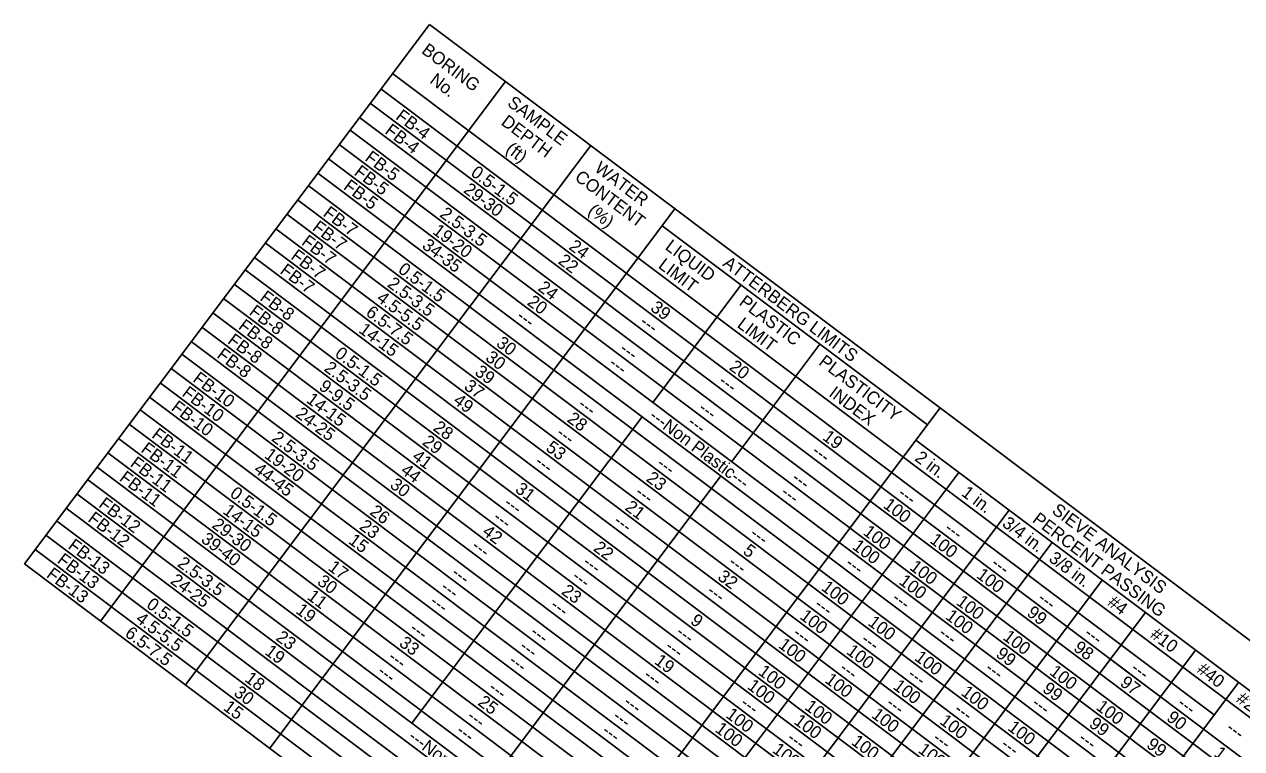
# Model space of a CAD drawing. Extents: x 627484.2 to 627517.5, y 367968.7 to 367996.9.
# Drawn here: x 627505.88 to 627511.18, y 367978.6 to 367981.76 of the extents above; entities that cross this region are included whole.
import ezdxf

# ---------------------------------------------------------------- set-up
doc = ezdxf.new("R2010")
doc.units = 0
doc.layers.add('Default', color=7, linetype='Continuous')
doc.layers.add('R_Survey Control', color=7, linetype='Continuous')

msp = doc.modelspace()

# ---------------------------------------------------------------- linework, layer by layer
at = {"layer": 'Default'}
for p, q in [((627505.8846, 367979.4086), (627507.6468, 367981.7554)), ((627507.6468, 367981.7554), (627512.1221, 367978.3948)), ((627507.4858, 367981.5409), (627511.9611, 367978.1804)), ((627506.216, 367979.1598), (627507.9782, 367981.5065)), ((627507.4361, 367981.4747), (627511.0615, 367978.7523)), ((627507.3892, 367981.4123), (627510.8275, 367978.8305)), ((627507.3424, 367981.3499), (627511.8177, 367977.9894)), ((627507.3014, 367981.2954), (627511.7767, 367977.9348)), ((627506.5863, 367978.8817), (627508.3485, 367981.2284)), ((627507.2546, 367981.233), (627511.7298, 367977.8725)), ((627507.2078, 367981.1706), (627511.683, 367977.8101)), ((627507.1609, 367981.1082), (627511.6362, 367977.7477)), ((627507.1199, 367981.0537), (627511.5952, 367977.6932)), ((627507.0731, 367980.9913), (627511.5483, 367977.6308)), ((627506.9528, 367978.6065), (627508.715, 367980.9533)), ((627507.0263, 367980.9289), (627511.5015, 367977.5684)), ((627508.6594, 367980.8792), (627509.8133, 367980.0127)), ((627506.9794, 367980.8665), (627511.4547, 367977.506)), ((627506.9326, 367980.8042), (627511.4078, 367977.4437)), ((627506.8858, 367980.7418), (627511.361, 367977.3813)), ((627506.8448, 367980.6872), (627511.32, 367977.3267)), ((627506.7979, 367980.6248), (627511.2732, 367977.2643)), ((627508.6189, 367980.1109), (627509.0024, 367980.6216)), ((627506.7511, 367980.5625), (627511.2264, 367977.202)), ((627506.7043, 367980.5001), (627511.1795, 367977.1396)), ((627506.6574, 367980.4377), (627511.1327, 367977.0772)), ((627506.6106, 367980.3754), (627511.0858, 367977.0149)), ((627508.962, 367979.8533), (627509.3455, 367980.364)), ((627506.5696, 367980.3208), (627511.0449, 367976.9603)), ((627506.5228, 367980.2584), (627510.998, 367976.8979)), ((627506.4759, 367980.196), (627510.9512, 367976.8355)), ((627506.4291, 367980.1337), (627510.9044, 367976.7732)), ((627508.1067, 367977.74), (627509.8689, 367980.0868)), ((627506.3881, 367980.0791), (627510.8634, 367976.7186)), ((627507.571, 367978.7153), (627508.5721, 367980.0486)), ((627506.3413, 367980.0167), (627510.8165, 367976.6562)), ((627506.2944, 367979.9543), (627510.7697, 367976.5938)), ((627509.7635, 367979.9465), (627511.354, 367978.7521)), ((627506.2476, 367979.892), (627510.7229, 367976.5315)), ((627506.2008, 367979.8296), (627510.676, 367976.4691)), ((627506.1598, 367979.775), (627510.635, 367976.4145)), ((627507.914, 367978.4577), (627508.9152, 367979.791)), ((627508.2938, 367977.5995), (627509.9506, 367979.806)), ((627506.113, 367979.7126), (627510.5882, 367976.3521)), ((627506.0661, 367979.6503), (627510.5414, 367976.2898)), ((627508.5121, 367977.4356), (627510.1689, 367979.642)), ((627506.0251, 367979.5957), (627510.5004, 367976.2352)), ((627505.9783, 367979.5333), (627510.4536, 367976.1728)), ((627508.6992, 367977.2951), (627510.356, 367979.5015)), ((627505.9315, 367979.4709), (627510.4067, 367976.1104)), ((627505.8846, 367979.4086), (627510.3599, 367976.0481)), ((627508.9175, 367977.1312), (627510.5743, 367979.3376)), ((627509.1046, 367976.9907), (627510.7615, 367979.1971)), ((627509.3229, 367976.8267), (627510.9798, 367979.0332)), ((627510.6092, 367978.9944), (627511.8645, 367978.0518)), ((627509.51, 367976.6862), (627511.1669, 367978.8927))]:
    msp.add_line(p, q, dxfattribs=at)
at = {"layer": 'R_Survey Control'}
msp.add_line((627507.6468, 367981.7554), (627507.6468, 367981.7554), dxfattribs=at)

# ---------------------------------------------------------------- texts
at = {"layer": 'Default'}
for s, p in [('BORING', (627507.6087, 367981.6335)), ('No.', (627507.6443, 367981.5037)), ('SAMPLE', (627507.9818, 367981.4049)), ('FB-4', (627507.4962, 367981.3464)), ('DEPTH', (627507.9549, 367981.322)), ('FB-4', (627507.4493, 367981.284)), ('FB-5', (627507.3625, 367981.1663)), ('(ft)', (627507.9748, 367981.2039)), ('FB-5', (627507.3157, 367981.1039)), ('0.5-1.5', (627507.8228, 367981.1011)), ('WATER', (627508.3611, 367981.1201)), ('CONTENT', (627508.2751, 367981.0816)), ('FB-5', (627507.2689, 367981.0416)), ('29-30', (627507.7912, 367981.0273)), ('FB-7', (627507.1804, 367980.9251)), ('2.5-3.5', (627507.6881, 367980.9218)), ('(%)', (627508.3323, 367980.9354)), ('FB-7', (627507.1335, 367980.8628)), ('19-20', (627507.6565, 367980.848)), ('FB-7', (627507.0867, 367980.8004)), ('34-35', (627507.6107, 367980.7849)), ('FB-7', (627507.0399, 367980.738)), ('24', (627508.2497, 367980.7806)), ('LIQUID', (627508.6685, 367980.7798)), ('FB-7', (627506.993, 367980.6756)), ('0.5-1.5', (627507.5066, 367980.6801)), ('22', (627508.2031, 367980.718)), ('LIMIT', (627508.6387, 367980.699)), ('ATTERBERG LIMITS', (627508.9191, 367980.7077)), ('2.5-3.5', (627507.4598, 367980.6177)), ('24', (627508.115, 367980.6012)), ('FB-8', (627506.9056, 367980.5584)), ('4.5-5.5', (627507.413, 367980.5554)), ('20', (627508.0682, 367980.5388)), ('PLASTIC', (627508.9903, 367980.5382)), ('FB-8', (627506.8588, 367980.496)), ('6.5-7.5', (627507.3661, 367980.493)), ('39', (627508.6047, 367980.514)), ('FB-8', (627506.8119, 367980.4336)), ('14-15', (627507.3355, 367980.4184)), ('---', (627508.0216, 367980.4764)), ('---', (627508.5578, 367980.4517)), ('LIMIT', (627508.9817, 367980.4414)), ('FB-8', (627506.7651, 367980.3713)), ('FB-8', (627506.7183, 367980.3089)), ('0.5-1.5', (627507.2315, 367980.3137)), ('30', (627507.9336, 367980.3595)), ('---', (627508.47, 367980.3347)), ('30', (627507.8868, 367980.2971)), ('20', (627508.9475, 367980.2566)), ('PLASTICITY', (627509.3365, 367980.2782)), ('FB-10', (627506.6135, 367980.2047)), ('2.5-3.5', (627507.1846, 367980.2513)), ('39', (627507.8401, 367980.2346)), ('---', (627508.4231, 367980.2723)), ('9-9.5', (627507.1622, 367980.1706)), ('37', (627507.7934, 367980.1722)), ('---', (627508.9008, 367980.1941)), ('FB-10', (627506.5667, 367980.1423)), ('14-15', (627507.1072, 367980.1144)), ('49', (627507.7465, 367980.1099)), ('INDEX', (627509.3808, 367980.1418)), ('FB-10', (627506.5198, 367980.0799)), ('24-25', (627507.0604, 367980.052)), ('---', (627508.2885, 367980.093)), ('---', (627508.813, 367980.0771)), ('28', (627507.6591, 367979.9926)), ('28', (627508.2422, 367980.0302)), ('---Non Plastic---', (627508.5986, 367980.0431)), ('---', (627508.7662, 367980.0147)), ('FB-11', (627506.4348, 367979.9608)), ('2.5-3.5', (627506.9563, 367979.9472)), ('---', (627508.1948, 367979.9683)), ('19', (627509.3532, 367979.9519)), ('FB-11', (627506.388, 367979.8985)), ('29', (627507.6118, 367979.9305)), ('53', (627508.1494, 367979.9049)), ('FB-11', (627506.3412, 367979.8361)), ('19-20', (627506.9247, 367979.8734)), ('41', (627507.5676, 367979.8662)), ('---', (627509.3063, 367979.8896)), ('2 in.', (627509.7545, 367979.8609)), ('44-45', (627506.8789, 367979.8103)), ('44', (627507.5179, 367979.806)), ('---', (627508.1011, 367979.8435)), ('---', (627508.6315, 367979.8354)), ('FB-11', (627506.2943, 367979.7737)), ('30', (627507.4711, 367979.7436)), ('23', (627508.5861, 367979.772)), ('---', (627509.2185, 367979.7727)), ('0.5-1.5', (627506.7748, 367979.7055)), ('31', (627508.016, 367979.7246)), ('---', (627508.5379, 367979.7107)), ('---', (627509.1716, 367979.7103)), ('---', (627509.6806, 367979.7061)), ('1 in.', (627509.9572, 367979.7087)), ('FB-12', (627506.2039, 367979.6588)), ('14-15', (627506.7442, 367979.631)), ('26', (627507.3833, 367979.6266)), ('---', (627507.9665, 367979.6642)), ('21', (627508.4937, 367979.6463)), ('100', (627509.6173, 367979.6561)), ('SIEVE ANALYSIS', (627510.3508, 367979.6324)), ('FB-12', (627506.157, 367979.5964)), ('29-30', (627506.6964, 367979.5694)), ('---', (627507.9197, 367979.6018)), ('---', (627508.4442, 367979.5859)), ('3/4 in.', (627510.1346, 367979.5755)), ('PERCENT PASSING', (627510.266, 367979.5929)), ('23', (627507.338, 367979.5631)), ('42', (627507.8729, 367979.5394)), ('100', (627509.5295, 367979.5391)), ('---', (627509.8833, 367979.5539)), ('FB-13', (627506.0706, 367979.4784)), ('39-40', (627506.6496, 367979.507)), ('15', (627507.2906, 367979.5012)), ('22', (627508.3564, 367979.469)), ('---', (627509.037, 367979.531)), ('100', (627509.4827, 367979.4767)), ('100', (627509.82, 367979.5038)), ('FB-13', (627506.0237, 367979.4161)), ('---', (627507.826, 367979.4771)), ('5', (627509.0072, 367979.4558)), ('3/8 in.', (627510.3373, 367979.4233)), ('FB-13', (627505.9769, 367979.3537)), ('2.5-3.5', (627506.5465, 367979.4015)), ('17', (627507.2021, 367979.3847)), ('---', (627508.3095, 367979.4066)), ('---', (627508.9433, 367979.4062)), ('---', (627509.4522, 367979.402)), ('100', (627509.7322, 367979.3869)), ('---', (627510.086, 367979.4017)), ('24-25', (627506.5159, 367979.3269)), ('30', (627507.1549, 367979.3226)), ('---', (627507.7382, 367979.3601)), ('---', (627508.2627, 367979.3442)), ('32', (627508.8965, 367979.3438)), ('100', (627509.6854, 367979.3245)), ('100', (627510.0227, 367979.3516)), ('11', (627507.1109, 367979.2581)), ('---', (627507.6913, 367979.2978)), ('23', (627508.2173, 367979.2808)), ('---', (627508.8496, 367979.2815)), ('100', (627509.348, 367979.2974)), ('0.5-1.5', (627506.4118, 367979.2222)), ('---', (627507.6445, 367979.2354)), ('---', (627508.169, 367979.2195)), ('---', (627509.3176, 367979.2227)), ('---', (627509.655, 367979.2498)), ('100', (627509.9349, 367979.2347)), ('---', (627510.2887, 367979.2495)), ('#4', (627510.5924, 367979.2318)), ('4.5-5.5', (627506.365, 367979.1598)), ('19', (627507.0615, 367979.1977)), ('9', (627508.7781, 367979.1523)), ('100', (627509.2543, 367979.1727)), ('100', (627509.8881, 367979.1723)), ('99', (627510.2419, 367979.187)), ('6.5-7.5', (627506.3182, 367979.0974)), ('---', (627507.5567, 367979.1184)), ('100', (627509.5507, 367979.1452)), ('#10', (627510.7787, 367979.0919)), ('23', (627506.975, 367979.0797)), ('33', (627507.5112, 367979.055)), ('---', (627508.0812, 367979.1025)), ('---', (627508.715, 367979.1022)), ('100', (627509.1607, 367979.0479)), ('---', (627509.2239, 367979.098)), ('---', (627509.5203, 367979.0705)), ('---', (627509.8577, 367979.0976)), ('100', (627510.1376, 367979.0825)), ('---', (627510.4914, 367979.0972)), ('19', (627506.9268, 367979.0183)), ('---', (627508.0344, 367979.0402)), ('---', (627508.6681, 367979.0398)), ('100', (627509.4571, 367979.0205)), ('100', (627509.7534, 367978.993)), ('99', (627510.1073, 367979.0077)), ('98', (627510.4451, 367979.0345)), ('---', (627507.463, 367978.9937)), ('---', (627507.9875, 367978.9778)), ('19', (627508.6214, 367978.9774)), ('#40', (627510.9814, 367978.9396)), ('18', (627506.8395, 367978.901)), ('---', (627507.4162, 367978.9313)), ('---', (627508.5745, 367978.9151)), ('100', (627509.0729, 367978.931)), ('100', (627509.3634, 367978.8957)), ('---', (627509.4266, 367978.9458)), ('---', (627509.723, 367978.9183)), ('---', (627510.0604, 367978.9454)), ('100', (627510.3404, 367978.9302)), ('97', (627510.6474, 367978.8825)), ('---', (627510.6941, 367978.945)), ('30', (627506.792, 367978.8392)), ('---', (627507.8997, 367978.8608)), ('100', (627509.026, 367978.8686)), ('100', (627509.6598, 367978.8682)), ('100', (627509.9562, 367978.8408)), ('99', (627510.31, 367978.8555)), ('15', (627506.7461, 367978.7761)), ('25', (627507.8537, 367978.7979)), ('---', (627508.4866, 367978.7981)), ('---', (627508.9956, 367978.7939)), ('100', (627509.2756, 367978.7788)), ('---', (627509.6293, 367978.7935)), ('---', (627510.2631, 367978.7932)), ('100', (627510.5431, 367978.778)), ('---', (627510.8968, 367978.7928)), ('#200', (627511.1522, 367978.8114)), ('100', (627508.9323, 367978.7439)), ('100', (627509.5661, 367978.7435)), ('---', (627509.9257, 367978.7661)), ('90', (627510.8498, 367978.7306)), ('---', (627507.8061, 367978.7361)), ('---', (627508.4398, 367978.7357)), ('100', (627508.8855, 367978.6815)), ('100', (627509.2287, 367978.7164)), ('100', (627509.8625, 367978.716)), ('100', (627510.1589, 367978.6885)), ('99', (627510.5127, 367978.7033)), ('---', (627511.1088, 367978.6854)), ('---Non Plastic---', (627507.5506, 367978.6475)), ('---', (627507.7592, 367978.6737)), ('---', (627508.393, 367978.6734)), ('---', (627509.1983, 367978.6417)), ('100', (627509.4783, 367978.6265)), ('---', (627509.832, 367978.6413)), ('---', (627510.4658, 367978.641)), ('99', (627510.7623, 367978.6134)), ('100', (627509.1351, 367978.5916)), ('100', (627509.7688, 367978.5913)), ('---', (627510.1284, 367978.6139)), ('1', (627511.056, 367978.5757))]:
    msp.add_text(s, height=0.055, rotation=323.0968, dxfattribs=at).set_placement(p)

doc.saveas('drawing.dxf')
